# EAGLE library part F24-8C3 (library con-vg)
CONNECTOR female, 24 pins + 8 coax, type C
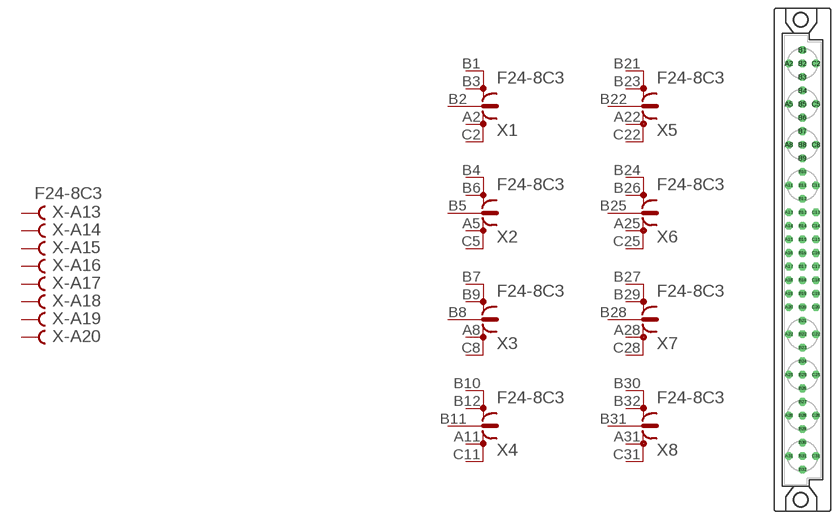
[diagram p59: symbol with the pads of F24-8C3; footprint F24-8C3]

Designator prefix X; gates 1=COAX 2=COAX 3=COAX 4=COAX 5=COAX 6=COAX 7=COAX 8=COAX -A13=FVAL -A14=FEM -A15=FEM -A16=FEM -A17=FEM -A18=FEM -A19=FEM -A20=FEM -C13=FVAL -C14=FEM -C15=FEM -C16=FEM -C17=FEM -C18=FEM -C19=FEM -C20=FEM -B13=FVAL -B14=FEM -B15=FEM -B16=FEM -B17=FEM -B18=FEM -B19=FEM -B20=FEM

## F24-8C3  [F24-8C3]
A2  1:S3  pas
A5  2:S3  pas
A8  3:S3  pas
A11  4:S3  pas
A13  -A13:B  pas
A14  -A14:B  pas
A15  -A15:B  pas
A16  -A16:B  pas
A17  -A17:B  pas
A18  -A18:B  pas
A19  -A19:B  pas
A20  -A20:B  pas
A22  5:S3  pas
A25  6:S3  pas
A28  7:S3  pas
A31  8:S3  pas
B1  1:S1  pas
B2  1:S  pas
B3  1:S2  pas
B4  2:S1  pas
B5  2:S  pas
B6  2:S2  pas
B7  3:S1  pas
B8  3:S  pas
B9  3:S2  pas
B10  4:S1  pas
B11  4:S  pas
B12  4:S2  pas
B13  -B13:B  pas
B14  -B14:B  pas
B15  -B15:B  pas
B16  -B16:B  pas
B17  -B17:B  pas
B18  -B18:B  pas
B19  -B19:B  pas
B20  -B20:B  pas
B21  5:S1  pas
B22  5:S  pas
B23  5:S2  pas
B24  6:S1  pas
B25  6:S  pas
B26  6:S2  pas
B27  7:S1  pas
B28  7:S  pas
B29  7:S2  pas
B30  8:S1  pas
B31  8:S  pas
B32  8:S2  pas
C2  1:S4  pas
C5  2:S4  pas
C8  3:S4  pas
C11  4:S4  pas
C13  -C13:B  pas
C14  -C14:B  pas
C15  -C15:B  pas
C16  -C16:B  pas
C17  -C17:B  pas
C18  -C18:B  pas
C19  -C19:B  pas
C20  -C20:B  pas
C22  5:S4  pas
C25  6:S4  pas
C28  7:S4  pas
C31  8:S4  pas

## Footprint F24-8C3 (pad centres in mm)
CONNECTOR female, 24 pins + 8 coax, type C
drill 0.914 octagon: A2 -2.54,36.83; A5 -2.54,29.21; A8 -2.54,21.59; A11 -2.54,13.97; A13 -2.54,8.89; A14 -2.54,6.35; A15 -2.54,3.81; A16 -2.54,1.27; A17 -2.54,-1.27; A18 -2.54,-3.81; A19 -2.54,-6.35; A20 -2.54,-8.89; A22 -2.54,-13.97; A25 -2.54,-21.59; A28 -2.54,-29.21; A31 -2.54,-36.83; B1 0,39.37; B2 0,36.83; B3 0,34.29; B4 0,31.75; B5 0,29.21; B6 0,26.67; B7 0,24.13; B8 0,21.59; B9 0,19.05; B10 0,16.51; B11 0,13.97; B12 0,11.43; B13 0,8.89; B14 0,6.35; B15 0,3.81; B16 0,1.27; B17 0,-1.27; B18 0,-3.81; B19 0,-6.35; B20 0,-8.89; B21 0,-11.43; B22 0,-13.97; B23 0,-16.51; B24 0,-19.05; B25 0,-21.59; B26 0,-24.13; B27 0,-26.67; B28 0,-29.21; B29 0,-31.75; B30 0,-34.29; B31 0,-36.83; B32 0,-39.37; C2 2.54,36.83; C5 2.54,29.21; C8 2.54,21.59; C11 2.54,13.97; C13 2.54,8.89; C14 2.54,6.35; C15 2.54,3.81; C16 2.54,1.27; C17 2.54,-1.27; C18 2.54,-3.81; C19 2.54,-6.35; C20 2.54,-8.89; C22 2.54,-13.97; C25 2.54,-21.59; C28 2.54,-29.21; C31 2.54,-36.83
hole 2.794 at -0.305,45.009
hole 2.794 at -0.305,-45.009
